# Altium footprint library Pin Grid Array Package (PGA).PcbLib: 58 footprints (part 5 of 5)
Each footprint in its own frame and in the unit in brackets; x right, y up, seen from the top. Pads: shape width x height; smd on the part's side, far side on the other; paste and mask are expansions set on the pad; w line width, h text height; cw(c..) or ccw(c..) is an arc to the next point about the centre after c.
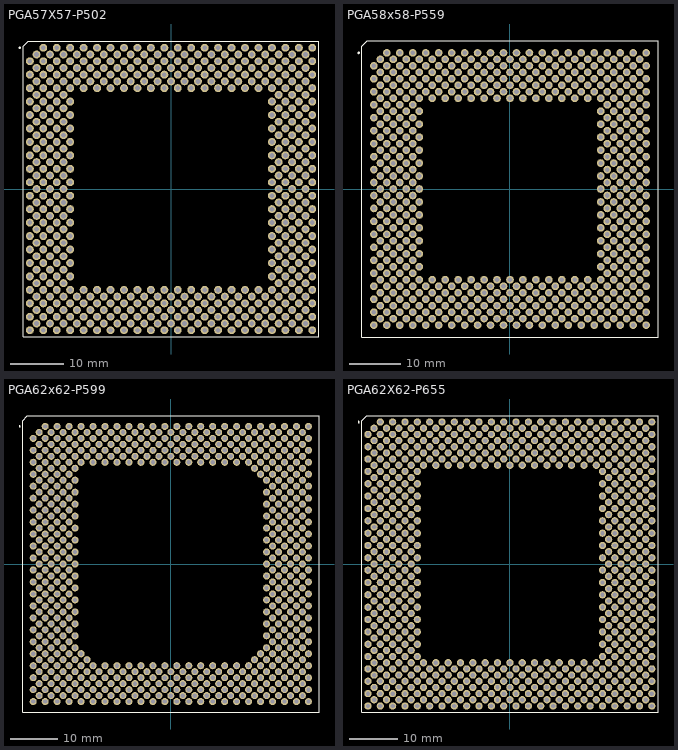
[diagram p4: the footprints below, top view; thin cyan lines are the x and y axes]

## PGA57X57-P502 [mm]
pads (503):
  round 1.5 hole 0.9: A3(-24.13,26.67) A5(-21.59,26.67) A7(-19.05,26.67) A9(-16.51,26.67) A11(-13.97,26.67) A13(-11.43,26.67) A15(-8.89,26.67) A17(-6.35,26.67) A19(-3.81,26.67) A21(-1.27,26.67) A23(1.27,26.67) A25(3.81,26.67) A27(6.35,26.67) A29(8.89,26.67) A31(11.43,26.67) A33(13.97,26.67) A35(16.51,26.67) A37(19.05,26.67) A39(21.59,26.67) A41(24.13,26.67) A43(26.67,26.67) AA1(-26.67,1.27) AA3(-24.13,1.27) AA5(-21.59,1.27) AA7(-19.05,1.27) AA37(19.05,1.27) AA39(21.59,1.27) AA41(24.13,1.27) AA43(26.67,1.27) AB2(-25.4,0) AB4(-22.86,0) AB6(-20.32,0) AB38(20.32,0) AB40(22.86,0) AB42(25.4,0) AC1(-26.67,-1.27) AC3(-24.13,-1.27) AC5(-21.59,-1.27) AC7(-19.05,-1.27) AC37(19.05,-1.27) AC39(21.59,-1.27) AC41(24.13,-1.27) AC43(26.67,-1.27) AD2(-25.4,-2.54) AD4(-22.86,-2.54) AD6(-20.32,-2.54) AD38(20.32,-2.54) AD40(22.86,-2.54) AD42(25.4,-2.54) AE1(-26.67,-3.81) AE3(-24.13,-3.81) AE5(-21.59,-3.81) AE7(-19.05,-3.81) AE37(19.05,-3.81) AE39(21.59,-3.81) AE41(24.13,-3.81) AE43(26.67,-3.81) AF2(-25.4,-5.08) AF4(-22.86,-5.08) AF6(-20.32,-5.08) AF38(20.32,-5.08) AF40(22.86,-5.08) AF42(25.4,-5.08) AG1(-26.67,-6.35) AG3(-24.13,-6.35) AG5(-21.59,-6.35) AG7(-19.05,-6.35) AG37(19.05,-6.35) AG39(21.59,-6.35) AG41(24.13,-6.35) AG43(26.67,-6.35) AH2(-25.4,-7.62) AH4(-22.86,-7.62) AH6(-20.32,-7.62) AH38(20.32,-7.62) AH40(22.86,-7.62) AH42(25.4,-7.62) AJ1(-26.67,-8.89) AJ3(-24.13,-8.89) AJ5(-21.59,-8.89) AJ7(-19.05,-8.89) AJ37(19.05,-8.89) AJ39(21.59,-8.89) AJ41(24.13,-8.89) AJ43(26.67,-8.89) AK2(-25.4,-10.16) AK4(-22.86,-10.16) AK6(-20.32,-10.16) AK38(20.32,-10.16) AK40(22.86,-10.16) AK42(25.4,-10.16) AL1(-26.67,-11.43) AL3(-24.13,-11.43) AL5(-21.59,-11.43) AL7(-19.05,-11.43) AL37(19.05,-11.43) AL39(21.59,-11.43) AL41(24.13,-11.43) AL43(26.67,-11.43) AM2(-25.4,-12.7) AM4(-22.86,-12.7) AM6(-20.32,-12.7) AM38(20.32,-12.7) AM40(22.86,-12.7) AM42(25.4,-12.7) AN1(-26.67,-13.97) AN3(-24.13,-13.97) AN5(-21.59,-13.97) AN7(-19.05,-13.97) AN37(19.05,-13.97) AN39(21.59,-13.97) AN41(24.13,-13.97) AN43(26.67,-13.97) AP2(-25.4,-15.24) AP4(-22.86,-15.24) AP6(-20.32,-15.24) AP38(20.32,-15.24) AP40(22.86,-15.24) AP42(25.4,-15.24) AR1(-26.67,-16.51) AR3(-24.13,-16.51) AR5(-21.59,-16.51) AR7(-19.05,-16.51) AR37(19.05,-16.51) AR39(21.59,-16.51) AR41(24.13,-16.51) AR43(26.67,-16.51) AT2(-25.4,-17.78) AT4(-22.86,-17.78) AT6(-20.32,-17.78) AT38(20.32,-17.78) AT40(22.86,-17.78) AT42(25.4,-17.78) AU1(-26.67,-19.05) AU3(-24.13,-19.05) AU5(-21.59,-19.05) AU7(-19.05,-19.05) AU9(-16.51,-19.05) AU11(-13.97,-19.05) AU13(-11.43,-19.05) AU15(-8.89,-19.05) AU17(-6.35,-19.05) AU19(-3.81,-19.05) AU21(-1.27,-19.05) AU23(1.27,-19.05) AU25(3.81,-19.05) AU27(6.35,-19.05) AU29(8.89,-19.05) AU31(11.43,-19.05) AU33(13.97,-19.05) AU35(16.51,-19.05) AU37(19.05,-19.05) AU39(21.59,-19.05) AU41(24.13,-19.05) AU43(26.67,-19.05) AV2(-25.4,-20.32) AV4(-22.86,-20.32) AV6(-20.32,-20.32) AV8(-17.78,-20.32) AV10(-15.24,-20.32) AV12(-12.7,-20.32) AV14(-10.16,-20.32) AV16(-7.62,-20.32) AV18(-5.08,-20.32) AV20(-2.54,-20.32) AV22(0,-20.32) AV24(2.54,-20.32) AV26(5.08,-20.32) AV28(7.62,-20.32) AV30(10.16,-20.32) AV32(12.7,-20.32) AV34(15.24,-20.32) AV36(17.78,-20.32) AV38(20.32,-20.32) AV40(22.86,-20.32) AV42(25.4,-20.32) AW1(-26.67,-21.59) AW3(-24.13,-21.59) AW5(-21.59,-21.59) AW7(-19.05,-21.59) AW9(-16.51,-21.59) AW11(-13.97,-21.59) AW13(-11.43,-21.59) AW15(-8.89,-21.59) AW17(-6.35,-21.59) AW19(-3.81,-21.59) AW21(-1.27,-21.59) AW23(1.27,-21.59) AW25(3.81,-21.59) AW27(6.35,-21.59) AW29(8.89,-21.59) AW31(11.43,-21.59) AW33(13.97,-21.59) AW35(16.51,-21.59) AW37(19.05,-21.59) AW39(21.59,-21.59) AW41(24.13,-21.59) AW43(26.67,-21.59) AY2(-25.4,-22.86) AY4(-22.86,-22.86) AY6(-20.32,-22.86) AY8(-17.78,-22.86) AY10(-15.24,-22.86) AY12(-12.7,-22.86) AY14(-10.16,-22.86) AY16(-7.62,-22.86) AY18(-5.08,-22.86) AY20(-2.54,-22.86) AY22(0,-22.86) AY24(2.54,-22.86) AY26(5.08,-22.86) AY28(7.62,-22.86) AY30(10.16,-22.86) AY32(12.7,-22.86) AY34(15.24,-22.86) AY36(17.78,-22.86) AY38(20.32,-22.86) AY40(22.86,-22.86) AY42(25.4,-22.86) B2(-25.4,25.4) B4(-22.86,25.4) B6(-20.32,25.4) B8(-17.78,25.4) B10(-15.24,25.4) B12(-12.7,25.4) B14(-10.16,25.4) B16(-7.62,25.4) B18(-5.08,25.4) B20(-2.54,25.4) B22(0,25.4) B24(2.54,25.4) B26(5.08,25.4) B28(7.62,25.4) B30(10.16,25.4) B32(12.7,25.4) B34(15.24,25.4) B36(17.78,25.4) B38(20.32,25.4) B40(22.86,25.4) B42(25.4,25.4) BA1(-26.67,-24.13) BA3(-24.13,-24.13) BA5(-21.59,-24.13) BA7(-19.05,-24.13) BA9(-16.51,-24.13) BA11(-13.97,-24.13) BA13(-11.43,-24.13) BA15(-8.89,-24.13) BA17(-6.35,-24.13) BA19(-3.81,-24.13) BA21(-1.27,-24.13) BA23(1.27,-24.13) BA25(3.81,-24.13) BA27(6.35,-24.13) BA29(8.89,-24.13) BA31(11.43,-24.13) BA33(13.97,-24.13) BA35(16.51,-24.13) BA37(19.05,-24.13) BA39(21.59,-24.13) BA41(24.13,-24.13) BA43(26.67,-24.13) BB2(-25.4,-25.4) BB4(-22.86,-25.4) BB6(-20.32,-25.4) BB8(-17.78,-25.4) BB10(-15.24,-25.4) BB12(-12.7,-25.4) BB14(-10.16,-25.4) BB16(-7.62,-25.4) BB18(-5.08,-25.4) BB20(-2.54,-25.4) BB22(0,-25.4) BB24(2.54,-25.4) BB26(5.08,-25.4) BB28(7.62,-25.4) BB30(10.16,-25.4) BB32(12.7,-25.4) BB34(15.24,-25.4) BB36(17.78,-25.4) BB38(20.32,-25.4) BB40(22.86,-25.4) BB42(25.4,-25.4) BC1(-26.67,-26.67) BC3(-24.13,-26.67) BC5(-21.59,-26.67) BC7(-19.05,-26.67) BC9(-16.51,-26.67) BC11(-13.97,-26.67) BC13(-11.43,-26.67) BC15(-8.89,-26.67) BC17(-6.35,-26.67) BC19(-3.81,-26.67) BC21(-1.27,-26.67) BC23(1.27,-26.67) BC25(3.81,-26.67) BC27(6.35,-26.67) BC29(8.89,-26.67) BC31(11.43,-26.67) BC33(13.97,-26.67) BC35(16.51,-26.67) BC37(19.05,-26.67) BC39(21.59,-26.67) BC41(24.13,-26.67) BC43(26.67,-26.67) C1(-26.67,24.13) C3(-24.13,24.13) C5(-21.59,24.13) C7(-19.05,24.13) C9(-16.51,24.13) C11(-13.97,24.13) C13(-11.43,24.13) C15(-8.89,24.13) C17(-6.35,24.13) C19(-3.81,24.13) C21(-1.27,24.13) C23(1.27,24.13) C25(3.81,24.13) C27(6.35,24.13) C29(8.89,24.13) C31(11.43,24.13) C33(13.97,24.13) C35(16.51,24.13) C37(19.05,24.13) C39(21.59,24.13) C41(24.13,24.13) C43(26.67,24.13) D2(-25.4,22.86) D4(-22.86,22.86) D6(-20.32,22.86) D8(-17.78,22.86) D10(-15.24,22.86) D12(-12.7,22.86) D14(-10.16,22.86) D16(-7.62,22.86) D18(-5.08,22.86) D20(-2.54,22.86) D22(0,22.86) D24(2.54,22.86) D26(5.08,22.86) D28(7.62,22.86) D30(10.16,22.86) D32(12.7,22.86) D34(15.24,22.86) D36(17.78,22.86) D38(20.32,22.86) D40(22.86,22.86) D42(25.4,22.86) E1(-26.67,21.59) E3(-24.13,21.59) E5(-21.59,21.59) E7(-19.05,21.59) E9(-16.51,21.59) E11(-13.97,21.59) E13(-11.43,21.59) E15(-8.89,21.59) E17(-6.35,21.59) E19(-3.81,21.59) E21(-1.27,21.59) E23(1.27,21.59) E25(3.81,21.59) E27(6.35,21.59) E29(8.89,21.59) E31(11.43,21.59) E33(13.97,21.59) E35(16.51,21.59) E37(19.05,21.59) E39(21.59,21.59) E41(24.13,21.59) E43(26.67,21.59) F2(-25.4,20.32) F4(-22.86,20.32) F6(-20.32,20.32) F8(-17.78,20.32) F10(-15.24,20.32) F12(-12.7,20.32) F14(-10.16,20.32) F16(-7.62,20.32) F18(-5.08,20.32) F20(-2.54,20.32) F22(0,20.32) F24(2.54,20.32) F26(5.08,20.32) F28(7.62,20.32) F30(10.16,20.32) F32(12.7,20.32) F34(15.24,20.32) F36(17.78,20.32) F38(20.32,20.32) F40(22.86,20.32) F42(25.4,20.32) G1(-26.67,19.05) G3(-24.13,19.05) G5(-21.59,19.05) G7(-19.05,19.05) G9(-16.51,19.05) G11(-13.97,19.05) G13(-11.43,19.05) G15(-8.89,19.05) G17(-6.35,19.05) G19(-3.81,19.05) G21(-1.27,19.05) G23(1.27,19.05) G25(3.81,19.05) G27(6.35,19.05) G29(8.89,19.05) G31(11.43,19.05) G33(13.97,19.05) G35(16.51,19.05) G37(19.05,19.05) G39(21.59,19.05) G41(24.13,19.05) G43(26.67,19.05) H2(-25.4,17.78) H4(-22.86,17.78) H6(-20.32,17.78) H38(20.32,17.78) H40(22.86,17.78) H42(25.4,17.78) J1(-26.67,16.51) J3(-24.13,16.51) J5(-21.59,16.51) J7(-19.05,16.51) J37(19.05,16.51) J39(21.59,16.51) J41(24.13,16.51) J43(26.67,16.51) K2(-25.4,15.24) K4(-22.86,15.24) K6(-20.32,15.24) K38(20.32,15.24) K40(22.86,15.24) K42(25.4,15.24) L1(-26.67,13.97) L3(-24.13,13.97) L5(-21.59,13.97) L7(-19.05,13.97) L37(19.05,13.97) L39(21.59,13.97) L41(24.13,13.97) L43(26.67,13.97) M2(-25.4,12.7) M4(-22.86,12.7) M6(-20.32,12.7) M38(20.32,12.7) M40(22.86,12.7) M42(25.4,12.7) N1(-26.67,11.43) N3(-24.13,11.43) N5(-21.59,11.43) N7(-19.05,11.43) N37(19.05,11.43) N39(21.59,11.43) N41(24.13,11.43) N43(26.67,11.43) P2(-25.4,10.16) P4(-22.86,10.16) P6(-20.32,10.16) P38(20.32,10.16) P40(22.86,10.16) P42(25.4,10.16) R1(-26.67,8.89) R3(-24.13,8.89) R5(-21.59,8.89) R7(-19.05,8.89) R37(19.05,8.89) R39(21.59,8.89) R41(24.13,8.89) R43(26.67,8.89) T2(-25.4,7.62) T4(-22.86,7.62) T6(-20.32,7.62) T38(20.32,7.62) T40(22.86,7.62) T42(25.4,7.62) U1(-26.67,6.35) U3(-24.13,6.35) U5(-21.59,6.35) U7(-19.05,6.35) U37(19.05,6.35) U39(21.59,6.35) U41(24.13,6.35) U43(26.67,6.35) V2(-25.4,5.08) V4(-22.86,5.08) V6(-20.32,5.08) V38(20.32,5.08) V40(22.86,5.08) V42(25.4,5.08) W1(-26.67,3.81) W3(-24.13,3.81) W5(-21.59,3.81) W7(-19.05,3.81) W37(19.05,3.81) W39(21.59,3.81) W41(24.13,3.81) W43(26.67,3.81) Y2(-25.4,2.54) Y4(-22.86,2.54) Y6(-20.32,2.54) Y38(20.32,2.54) Y40(22.86,2.54) Y42(25.4,2.54)
Top Overlay:
  circle w0.25: c-28.59,26.67 r0.125
  lines w0.2: -27.94,-27.94 -27.94,26.94 -26.94,27.94 27.94,27.94 27.94,-27.94 -27.94,-27.94

## PGA58x58-P559 [mm]
pads (559):
  round 1.5 hole 0.9: A3(-24.13,26.67) A5(-21.59,26.67) A7(-19.05,26.67) A9(-16.51,26.67) A11(-13.97,26.67) A13(-11.43,26.67) A15(-8.89,26.67) A17(-6.35,26.67) A19(-3.81,26.67) A21(-1.27,26.67) A23(1.27,26.67) A25(3.81,26.67) A27(6.35,26.67) A29(8.89,26.67) A31(11.43,26.67) A33(13.97,26.67) A35(16.51,26.67) A37(19.05,26.67) A39(21.59,26.67) A41(24.13,26.67) A43(26.67,26.67) AA1(-26.67,1.27) AA3(-24.13,1.27) AA5(-21.59,1.27) AA7(-19.05,1.27) AA37(19.05,1.27) AA39(21.59,1.27) AA41(24.13,1.27) AA43(26.67,1.27) AB2(-25.4,0) AB4(-22.86,0) AB6(-20.32,0) AB8(-17.78,0) AB36(17.78,0) AB38(20.32,0) AB40(22.86,0) AB42(25.4,0) AC1(-26.67,-1.27) AC3(-24.13,-1.27) AC5(-21.59,-1.27) AC7(-19.05,-1.27) AC37(19.05,-1.27) AC39(21.59,-1.27) AC41(24.13,-1.27) AC43(26.67,-1.27) AD2(-25.4,-2.54) AD4(-22.86,-2.54) AD6(-20.32,-2.54) AD8(-17.78,-2.54) AD36(17.78,-2.54) AD38(20.32,-2.54) AD40(22.86,-2.54) AD42(25.4,-2.54) AE1(-26.67,-3.81) AE3(-24.13,-3.81) AE5(-21.59,-3.81) AE7(-19.05,-3.81) AE37(19.05,-3.81) AE39(21.59,-3.81) AE41(24.13,-3.81) AE43(26.67,-3.81) AF2(-25.4,-5.08) AF4(-22.86,-5.08) AF6(-20.32,-5.08) AF8(-17.78,-5.08) AF36(17.78,-5.08) AF38(20.32,-5.08) AF40(22.86,-5.08) AF42(25.4,-5.08) AG1(-26.67,-6.35) AG3(-24.13,-6.35) AG5(-21.59,-6.35) AG7(-19.05,-6.35) AG37(19.05,-6.35) AG39(21.59,-6.35) AG41(24.13,-6.35) AG43(26.67,-6.35) AH2(-25.4,-7.62) AH4(-22.86,-7.62) AH6(-20.32,-7.62) AH8(-17.78,-7.62) AH36(17.78,-7.62) AH38(20.32,-7.62) AH40(22.86,-7.62) AH42(25.4,-7.62) AJ1(-26.67,-8.89) AJ3(-24.13,-8.89) AJ5(-21.59,-8.89) AJ7(-19.05,-8.89) AJ37(19.05,-8.89) AJ39(21.59,-8.89) AJ41(24.13,-8.89) AJ43(26.67,-8.89) AK2(-25.4,-10.16) AK4(-22.86,-10.16) AK6(-20.32,-10.16) AK8(-17.78,-10.16) AK36(17.78,-10.16) AK38(20.32,-10.16) AK40(22.86,-10.16) AK42(25.4,-10.16) AL1(-26.67,-11.43) AL3(-24.13,-11.43) AL5(-21.59,-11.43) AL7(-19.05,-11.43) AL37(19.05,-11.43) AL39(21.59,-11.43) AL41(24.13,-11.43) AL43(26.67,-11.43) AM2(-25.4,-12.7) AM4(-22.86,-12.7) AM6(-20.32,-12.7) AM8(-17.78,-12.7) AM36(17.78,-12.7) AM38(20.32,-12.7) AM40(22.86,-12.7) AM42(25.4,-12.7) AN1(-26.67,-13.97) AN3(-24.13,-13.97) AN5(-21.59,-13.97) AN7(-19.05,-13.97) AN37(19.05,-13.97) AN39(21.59,-13.97) AN41(24.13,-13.97) AN43(26.67,-13.97) AP2(-25.4,-15.24) AP4(-22.86,-15.24) AP6(-20.32,-15.24) AP8(-17.78,-15.24) AP36(17.78,-15.24) AP38(20.32,-15.24) AP40(22.86,-15.24) AP42(25.4,-15.24) AR1(-26.67,-16.51) AR3(-24.13,-16.51) AR5(-21.59,-16.51) AR7(-19.05,-16.51) AR37(19.05,-16.51) AR39(21.59,-16.51) AR41(24.13,-16.51) AR43(26.67,-16.51) AT2(-25.4,-17.78) AT4(-22.86,-17.78) AT6(-20.32,-17.78) AT8(-17.78,-17.78) AT10(-15.24,-17.78) AT12(-12.7,-17.78) AT14(-10.16,-17.78) AT16(-7.62,-17.78) AT18(-5.08,-17.78) AT20(-2.54,-17.78) AT22(0,-17.78) AT24(2.54,-17.78) AT26(5.08,-17.78) AT28(7.62,-17.78) AT30(10.16,-17.78) AT32(12.7,-17.78) AT34(15.24,-17.78) AT36(17.78,-17.78) AT38(20.32,-17.78) AT40(22.86,-17.78) AT42(25.4,-17.78) AU1(-26.67,-19.05) AU3(-24.13,-19.05) AU5(-21.59,-19.05) AU7(-19.05,-19.05) AU9(-16.51,-19.05) AU11(-13.97,-19.05) AU13(-11.43,-19.05) AU15(-8.89,-19.05) AU17(-6.35,-19.05) AU19(-3.81,-19.05) AU21(-1.27,-19.05) AU23(1.27,-19.05) AU25(3.81,-19.05) AU27(6.35,-19.05) AU29(8.89,-19.05) AU31(11.43,-19.05) AU33(13.97,-19.05) AU35(16.51,-19.05) AU37(19.05,-19.05) AU39(21.59,-19.05) AU41(24.13,-19.05) AU43(26.67,-19.05) AV2(-25.4,-20.32) AV4(-22.86,-20.32) AV6(-20.32,-20.32) AV8(-17.78,-20.32) AV10(-15.24,-20.32) AV12(-12.7,-20.32) AV14(-10.16,-20.32) AV16(-7.62,-20.32) AV18(-5.08,-20.32) AV20(-2.54,-20.32) AV22(0,-20.32) AV24(2.54,-20.32) AV26(5.08,-20.32) AV28(7.62,-20.32) AV30(10.16,-20.32) AV32(12.7,-20.32) AV34(15.24,-20.32) AV36(17.78,-20.32) AV38(20.32,-20.32) AV40(22.86,-20.32) AV42(25.4,-20.32) AW1(-26.67,-21.59) AW3(-24.13,-21.59) AW5(-21.59,-21.59) AW7(-19.05,-21.59) AW9(-16.51,-21.59) AW11(-13.97,-21.59) AW13(-11.43,-21.59) AW15(-8.89,-21.59) AW17(-6.35,-21.59) AW19(-3.81,-21.59) AW21(-1.27,-21.59) AW23(1.27,-21.59) AW25(3.81,-21.59) AW27(6.35,-21.59) AW29(8.89,-21.59) AW31(11.43,-21.59) AW33(13.97,-21.59) AW35(16.51,-21.59) AW37(19.05,-21.59) AW39(21.59,-21.59) AW41(24.13,-21.59) AW43(26.67,-21.59) AY2(-25.4,-22.86) AY4(-22.86,-22.86) AY6(-20.32,-22.86) AY8(-17.78,-22.86) AY10(-15.24,-22.86) AY12(-12.7,-22.86) AY14(-10.16,-22.86) AY16(-7.62,-22.86) AY18(-5.08,-22.86) AY20(-2.54,-22.86) AY22(0,-22.86) AY24(2.54,-22.86) AY26(5.08,-22.86) AY28(7.62,-22.86) AY30(10.16,-22.86) AY32(12.7,-22.86) AY34(15.24,-22.86) AY36(17.78,-22.86) AY38(20.32,-22.86) AY40(22.86,-22.86) AY42(25.4,-22.86) B2(-25.4,25.4) B4(-22.86,25.4) B6(-20.32,25.4) B8(-17.78,25.4) B10(-15.24,25.4) B12(-12.7,25.4) B14(-10.16,25.4) B16(-7.62,25.4) B18(-5.08,25.4) B20(-2.54,25.4) B22(0,25.4) B24(2.54,25.4) B26(5.08,25.4) B28(7.62,25.4) B30(10.16,25.4) B32(12.7,25.4) B34(15.24,25.4) B36(17.78,25.4) B38(20.32,25.4) B40(22.86,25.4) B42(25.4,25.4) BA1(-26.67,-24.13) BA3(-24.13,-24.13) BA5(-21.59,-24.13) BA7(-19.05,-24.13) BA9(-16.51,-24.13) BA11(-13.97,-24.13) BA13(-11.43,-24.13) BA15(-8.89,-24.13) BA17(-6.35,-24.13) BA19(-3.81,-24.13) BA21(-1.27,-24.13) BA23(1.27,-24.13) BA25(3.81,-24.13) BA27(6.35,-24.13) BA29(8.89,-24.13) BA31(11.43,-24.13) BA33(13.97,-24.13) BA35(16.51,-24.13) BA37(19.05,-24.13) BA39(21.59,-24.13) BA41(24.13,-24.13) BA43(26.67,-24.13) BB2(-25.4,-25.4) BB4(-22.86,-25.4) BB6(-20.32,-25.4) BB8(-17.78,-25.4) BB10(-15.24,-25.4) BB12(-12.7,-25.4) BB14(-10.16,-25.4) BB16(-7.62,-25.4) BB18(-5.08,-25.4) BB20(-2.54,-25.4) BB22(0,-25.4) BB24(2.54,-25.4) BB26(5.08,-25.4) BB28(7.62,-25.4) BB30(10.16,-25.4) BB32(12.7,-25.4) BB34(15.24,-25.4) BB36(17.78,-25.4) BB38(20.32,-25.4) BB40(22.86,-25.4) BB42(25.4,-25.4) BC1(-26.67,-26.67) BC3(-24.13,-26.67) BC5(-21.59,-26.67) BC7(-19.05,-26.67) BC9(-16.51,-26.67) BC11(-13.97,-26.67) BC13(-11.43,-26.67) BC15(-8.89,-26.67) BC17(-6.35,-26.67) BC19(-3.81,-26.67) BC21(-1.27,-26.67) BC23(1.27,-26.67) BC25(3.81,-26.67) BC27(6.35,-26.67) BC29(8.89,-26.67) BC31(11.43,-26.67) BC33(13.97,-26.67) BC35(16.51,-26.67) BC37(19.05,-26.67) BC39(21.59,-26.67) BC41(24.13,-26.67) BC43(26.67,-26.67) C1(-26.67,24.13) C3(-24.13,24.13) C5(-21.59,24.13) C7(-19.05,24.13) C9(-16.51,24.13) C11(-13.97,24.13) C13(-11.43,24.13) C15(-8.89,24.13) C17(-6.35,24.13) C19(-3.81,24.13) C21(-1.27,24.13) C23(1.27,24.13) C25(3.81,24.13) C27(6.35,24.13) C29(8.89,24.13) C31(11.43,24.13) C33(13.97,24.13) C35(16.51,24.13) C37(19.05,24.13) C39(21.59,24.13) C41(24.13,24.13) C43(26.67,24.13) D2(-25.4,22.86) D4(-22.86,22.86) D6(-20.32,22.86) D8(-17.78,22.86) D10(-15.24,22.86) D12(-12.7,22.86) D14(-10.16,22.86) D16(-7.62,22.86) D18(-5.08,22.86) D20(-2.54,22.86) D22(0,22.86) D24(2.54,22.86) D26(5.08,22.86) D28(7.62,22.86) D30(10.16,22.86) D32(12.7,22.86) D34(15.24,22.86) D36(17.78,22.86) D38(20.32,22.86) D40(22.86,22.86) D42(25.4,22.86) E1(-26.67,21.59) E3(-24.13,21.59) E5(-21.59,21.59) E7(-19.05,21.59) E9(-16.51,21.59) E11(-13.97,21.59) E13(-11.43,21.59) E15(-8.89,21.59) E17(-6.35,21.59) E19(-3.81,21.59) E21(-1.27,21.59) E23(1.27,21.59) E25(3.81,21.59) E27(6.35,21.59) E29(8.89,21.59) E31(11.43,21.59) E33(13.97,21.59) E35(16.51,21.59) E37(19.05,21.59) E39(21.59,21.59) E41(24.13,21.59) E43(26.67,21.59) F2(-25.4,20.32) F4(-22.86,20.32) F6(-20.32,20.32) F8(-17.78,20.32) F10(-15.24,20.32) F12(-12.7,20.32) F14(-10.16,20.32) F16(-7.62,20.32) F18(-5.08,20.32) F20(-2.54,20.32) F22(0,20.32) F24(2.54,20.32) F26(5.08,20.32) F28(7.62,20.32) F30(10.16,20.32) F32(12.7,20.32) F34(15.24,20.32) F36(17.78,20.32) F38(20.32,20.32) F40(22.86,20.32) F42(25.4,20.32) G1(-26.67,19.05) G3(-24.13,19.05) G5(-21.59,19.05) G7(-19.05,19.05) G9(-16.51,19.05) G11(-13.97,19.05) G13(-11.43,19.05) G15(-8.89,19.05) G17(-6.35,19.05) G19(-3.81,19.05) G21(-1.27,19.05) G23(1.27,19.05) G25(3.81,19.05) G27(6.35,19.05) G29(8.89,19.05) G31(11.43,19.05) G33(13.97,19.05) G35(16.51,19.05) G37(19.05,19.05) G39(21.59,19.05) G41(24.13,19.05) G43(26.67,19.05) H2(-25.4,17.78) H4(-22.86,17.78) H6(-20.32,17.78) H8(-17.78,17.78) H10(-15.24,17.78) H12(-12.7,17.78) H14(-10.16,17.78) H16(-7.62,17.78) H18(-5.08,17.78) H20(-2.54,17.78) H22(0,17.78) H24(2.54,17.78) H26(5.08,17.78) H28(7.62,17.78) H30(10.16,17.78) H32(12.7,17.78) H34(15.24,17.78) H36(17.78,17.78) H38(20.32,17.78) H40(22.86,17.78) H42(25.4,17.78) J1(-26.67,16.51) J3(-24.13,16.51) J5(-21.59,16.51) J7(-19.05,16.51) J37(19.05,16.51) J39(21.59,16.51) J41(24.13,16.51) J43(26.67,16.51) K2(-25.4,15.24) K4(-22.86,15.24) K6(-20.32,15.24) K8(-17.78,15.24) K36(17.78,15.24) K38(20.32,15.24) K40(22.86,15.24) K42(25.4,15.24) L1(-26.67,13.97) L3(-24.13,13.97) L5(-21.59,13.97) L7(-19.05,13.97) L37(19.05,13.97) L39(21.59,13.97) L41(24.13,13.97) L43(26.67,13.97) M2(-25.4,12.7) M4(-22.86,12.7) M6(-20.32,12.7) M8(-17.78,12.7) M36(17.78,12.7) M38(20.32,12.7) M40(22.86,12.7) M42(25.4,12.7) N1(-26.67,11.43) N3(-24.13,11.43) N5(-21.59,11.43) N7(-19.05,11.43) N37(19.05,11.43) N39(21.59,11.43) N41(24.13,11.43) N43(26.67,11.43) P2(-25.4,10.16) P4(-22.86,10.16) P6(-20.32,10.16) P8(-17.78,10.16) P36(17.78,10.16) P38(20.32,10.16) P40(22.86,10.16) P42(25.4,10.16) R1(-26.67,8.89) R3(-24.13,8.89) R5(-21.59,8.89) R7(-19.05,8.89) R37(19.05,8.89) R39(21.59,8.89) R41(24.13,8.89) R43(26.67,8.89) T2(-25.4,7.62) T4(-22.86,7.62) T6(-20.32,7.62) T8(-17.78,7.62) T36(17.78,7.62) T38(20.32,7.62) T40(22.86,7.62) T42(25.4,7.62) U1(-26.67,6.35) U3(-24.13,6.35) U5(-21.59,6.35) U7(-19.05,6.35) U37(19.05,6.35) U39(21.59,6.35) U41(24.13,6.35) U43(26.67,6.35) V2(-25.4,5.08) V4(-22.86,5.08) V6(-20.32,5.08) V8(-17.78,5.08) V36(17.78,5.08) V38(20.32,5.08) V40(22.86,5.08) V42(25.4,5.08) W1(-26.67,3.81) W3(-24.13,3.81) W5(-21.59,3.81) W7(-19.05,3.81) W37(19.05,3.81) W39(21.59,3.81) W41(24.13,3.81) W43(26.67,3.81) Y2(-25.4,2.54) Y4(-22.86,2.54) Y6(-20.32,2.54) Y8(-17.78,2.54) Y36(17.78,2.54) Y38(20.32,2.54) Y40(22.86,2.54) Y42(25.4,2.54)
Top Overlay:
  circle w0.25: c-29.65,26.67 r0.125
  lines w0.2: -29,-29 29,-29 29,29 -28,29 -29,28 -29,-29

## PGA62x62-P599 [mm]
pads (599):
  round 1.5 hole 0.9: A3(-26.67,29.21) A5(-24.13,29.21) A7(-21.59,29.21) A9(-19.05,29.21) A11(-16.51,29.21) A13(-13.97,29.21) A15(-11.43,29.21) A17(-8.89,29.21) A19(-6.35,29.21) A21(-3.81,29.21) A23(-1.27,29.21) A25(1.27,29.21) A27(3.81,29.21) A29(6.35,29.21) A31(8.89,29.21) A33(11.43,29.21) A35(13.97,29.21) A37(16.51,29.21) A39(19.05,29.21) A41(21.59,29.21) A43(24.13,29.21) A45(26.67,29.21) A47(29.21,29.21) AA1(-29.21,3.81) AA3(-26.67,3.81) AA5(-24.13,3.81) AA7(-21.59,3.81) AA41(21.59,3.81) AA43(24.13,3.81) AA45(26.67,3.81) AA47(29.21,3.81) AB2(-27.94,2.54) AB4(-25.4,2.54) AB6(-22.86,2.54) AB8(-20.32,2.54) AB40(20.32,2.54) AB42(22.86,2.54) AB44(25.4,2.54) AB46(27.94,2.54) AC1(-29.21,1.27) AC3(-26.67,1.27) AC5(-24.13,1.27) AC7(-21.59,1.27) AC41(21.59,1.27) AC43(24.13,1.27) AC45(26.67,1.27) AC47(29.21,1.27) AD2(-27.94,0) AD4(-25.4,0) AD6(-22.86,0) AD8(-20.32,0) AD40(20.32,0) AD42(22.86,0) AD44(25.4,0) AD46(27.94,0) AE1(-29.21,-1.27) AE3(-26.67,-1.27) AE5(-24.13,-1.27) AE7(-21.59,-1.27) AE41(21.59,-1.27) AE43(24.13,-1.27) AE45(26.67,-1.27) AE47(29.21,-1.27) AF2(-27.94,-2.54) AF4(-25.4,-2.54) AF6(-22.86,-2.54) AF8(-20.32,-2.54) AF40(20.32,-2.54) AF42(22.86,-2.54) AF44(25.4,-2.54) AF46(27.94,-2.54) AG1(-29.21,-3.81) AG3(-26.67,-3.81) AG5(-24.13,-3.81) AG7(-21.59,-3.81) AG41(21.59,-3.81) AG43(24.13,-3.81) AG45(26.67,-3.81) AG47(29.21,-3.81) AH2(-27.94,-5.08) AH4(-25.4,-5.08) AH6(-22.86,-5.08) AH8(-20.32,-5.08) AH40(20.32,-5.08) AH42(22.86,-5.08) AH44(25.4,-5.08) AH46(27.94,-5.08) AJ1(-29.21,-6.35) AJ3(-26.67,-6.35) AJ5(-24.13,-6.35) AJ7(-21.59,-6.35) AJ41(21.59,-6.35) AJ43(24.13,-6.35) AJ45(26.67,-6.35) AJ47(29.21,-6.35) AK2(-27.94,-7.62) AK4(-25.4,-7.62) AK6(-22.86,-7.62) AK8(-20.32,-7.62) AK40(20.32,-7.62) AK42(22.86,-7.62) AK44(25.4,-7.62) AK46(27.94,-7.62) AL1(-29.21,-8.89) AL3(-26.67,-8.89) AL5(-24.13,-8.89) AL7(-21.59,-8.89) AL41(21.59,-8.89) AL43(24.13,-8.89) AL45(26.67,-8.89) AL47(29.21,-8.89) AM2(-27.94,-10.16) AM4(-25.4,-10.16) AM6(-22.86,-10.16) AM8(-20.32,-10.16) AM40(20.32,-10.16) AM42(22.86,-10.16) AM44(25.4,-10.16) AM46(27.94,-10.16) AN1(-29.21,-11.43) AN3(-26.67,-11.43) AN5(-24.13,-11.43) AN7(-21.59,-11.43) AN41(21.59,-11.43) AN43(24.13,-11.43) AN45(26.67,-11.43) AN47(29.21,-11.43) AP2(-27.94,-12.7) AP4(-25.4,-12.7) AP6(-22.86,-12.7) AP8(-20.32,-12.7) AP40(20.32,-12.7) AP42(22.86,-12.7) AP44(25.4,-12.7) AP46(27.94,-12.7) AR1(-29.21,-13.97) AR3(-26.67,-13.97) AR5(-24.13,-13.97) AR7(-21.59,-13.97) AR41(21.59,-13.97) AR43(24.13,-13.97) AR45(26.67,-13.97) AR47(29.21,-13.97) AT2(-27.94,-15.24) AT4(-25.4,-15.24) AT6(-22.86,-15.24) AT8(-20.32,-15.24) AT40(20.32,-15.24) AT42(22.86,-15.24) AT44(25.4,-15.24) AT46(27.94,-15.24) AU1(-29.21,-16.51) AU3(-26.67,-16.51) AU5(-24.13,-16.51) AU7(-21.59,-16.51) AU41(21.59,-16.51) AU43(24.13,-16.51) AU45(26.67,-16.51) AU47(29.21,-16.51) AV2(-27.94,-17.78) AV4(-25.4,-17.78) AV6(-22.86,-17.78) AV8(-20.32,-17.78) AV40(20.32,-17.78) AV42(22.86,-17.78) AV44(25.4,-17.78) AV46(27.94,-17.78) AW1(-29.21,-19.05) AW3(-26.67,-19.05) AW5(-24.13,-19.05) AW7(-21.59,-19.05) AW9(-19.05,-19.05) AW39(19.05,-19.05) AW41(21.59,-19.05) AW43(24.13,-19.05) AW45(26.67,-19.05) AW47(29.21,-19.05) AY2(-27.94,-20.32) AY4(-25.4,-20.32) AY6(-22.86,-20.32) AY8(-20.32,-20.32) AY10(-17.78,-20.32) AY38(17.78,-20.32) AY40(20.32,-20.32) AY42(22.86,-20.32) AY44(25.4,-20.32) AY46(27.94,-20.32) B2(-27.94,27.94) B4(-25.4,27.94) B6(-22.86,27.94) B8(-20.32,27.94) B10(-17.78,27.94) B12(-15.24,27.94) B14(-12.7,27.94) B16(-10.16,27.94) B18(-7.62,27.94) B20(-5.08,27.94) B22(-2.54,27.94) B24(0,27.94) B26(2.54,27.94) B28(5.08,27.94) B30(7.62,27.94) B32(10.16,27.94) B34(12.7,27.94) B36(15.24,27.94) B38(17.78,27.94) B40(20.32,27.94) B42(22.86,27.94) B44(25.4,27.94) B46(27.94,27.94) BA1(-29.21,-21.59) BA3(-26.67,-21.59) BA5(-24.13,-21.59) BA7(-21.59,-21.59) BA9(-19.05,-21.59) BA11(-16.51,-21.59) BA13(-13.97,-21.59) BA15(-11.43,-21.59) BA17(-8.89,-21.59) BA19(-6.35,-21.59) BA21(-3.81,-21.59) BA23(-1.27,-21.59) BA25(1.27,-21.59) BA27(3.81,-21.59) BA29(6.35,-21.59) BA31(8.89,-21.59) BA33(11.43,-21.59) BA35(13.97,-21.59) BA37(16.51,-21.59) BA39(19.05,-21.59) BA41(21.59,-21.59) BA43(24.13,-21.59) BA45(26.67,-21.59) BA47(29.21,-21.59) BB2(-27.94,-22.86) BB4(-25.4,-22.86) BB6(-22.86,-22.86) BB8(-20.32,-22.86) BB10(-17.78,-22.86) BB12(-15.24,-22.86) BB14(-12.7,-22.86) BB16(-10.16,-22.86) BB18(-7.62,-22.86) BB20(-5.08,-22.86) BB22(-2.54,-22.86) BB24(0,-22.86) BB26(2.54,-22.86) BB28(5.08,-22.86) BB30(7.62,-22.86) BB32(10.16,-22.86) BB34(12.7,-22.86) BB36(15.24,-22.86) BB38(17.78,-22.86) BB40(20.32,-22.86) BB42(22.86,-22.86) BB44(25.4,-22.86) BB46(27.94,-22.86) BC1(-29.21,-24.13) BC3(-26.67,-24.13) BC5(-24.13,-24.13) BC7(-21.59,-24.13) BC9(-19.05,-24.13) BC11(-16.51,-24.13) BC13(-13.97,-24.13) BC15(-11.43,-24.13) BC17(-8.89,-24.13) BC19(-6.35,-24.13) BC21(-3.81,-24.13) BC23(-1.27,-24.13) BC25(1.27,-24.13) BC27(3.81,-24.13) BC29(6.35,-24.13) BC31(8.89,-24.13) BC33(11.43,-24.13) BC35(13.97,-24.13) BC37(16.51,-24.13) BC39(19.05,-24.13) BC41(21.59,-24.13) BC43(24.13,-24.13) BC45(26.67,-24.13) BC47(29.21,-24.13) BD2(-27.94,-25.4) BD4(-25.4,-25.4) BD6(-22.86,-25.4) BD8(-20.32,-25.4) BD10(-17.78,-25.4) BD12(-15.24,-25.4) BD14(-12.7,-25.4) BD16(-10.16,-25.4) BD18(-7.62,-25.4) BD20(-5.08,-25.4) BD22(-2.54,-25.4) BD24(0,-25.4) BD26(2.54,-25.4) BD28(5.08,-25.4) BD30(7.62,-25.4) BD32(10.16,-25.4) BD34(12.7,-25.4) BD36(15.24,-25.4) BD38(17.78,-25.4) BD40(20.32,-25.4) BD42(22.86,-25.4) BD44(25.4,-25.4) BD46(27.94,-25.4) BE1(-29.21,-26.67) BE3(-26.67,-26.67) BE5(-24.13,-26.67) BE7(-21.59,-26.67) BE9(-19.05,-26.67) BE11(-16.51,-26.67) BE13(-13.97,-26.67) BE15(-11.43,-26.67) BE17(-8.89,-26.67) BE19(-6.35,-26.67) BE21(-3.81,-26.67) BE23(-1.27,-26.67) BE25(1.27,-26.67) BE27(3.81,-26.67) BE29(6.35,-26.67) BE31(8.89,-26.67) BE33(11.43,-26.67) BE35(13.97,-26.67) BE37(16.51,-26.67) BE39(19.05,-26.67) BE41(21.59,-26.67) BE43(24.13,-26.67) BE45(26.67,-26.67) BE47(29.21,-26.67) BF2(-27.94,-27.94) BF4(-25.4,-27.94) BF6(-22.86,-27.94) BF8(-20.32,-27.94) BF10(-17.78,-27.94) BF12(-15.24,-27.94) BF14(-12.7,-27.94) BF16(-10.16,-27.94) BF18(-7.62,-27.94) BF20(-5.08,-27.94) BF22(-2.54,-27.94) BF24(0,-27.94) BF26(2.54,-27.94) BF28(5.08,-27.94) BF30(7.62,-27.94) BF32(10.16,-27.94) BF34(12.7,-27.94) BF36(15.24,-27.94) BF38(17.78,-27.94) BF40(20.32,-27.94) BF42(22.86,-27.94) BF44(25.4,-27.94) BF46(27.94,-27.94) BG1(-29.21,-29.21) BG3(-26.67,-29.21) BG5(-24.13,-29.21) BG7(-21.59,-29.21) BG9(-19.05,-29.21) BG11(-16.51,-29.21) BG13(-13.97,-29.21) BG15(-11.43,-29.21) BG17(-8.89,-29.21) BG19(-6.35,-29.21) BG21(-3.81,-29.21) BG23(-1.27,-29.21) BG25(1.27,-29.21) BG27(3.81,-29.21) BG29(6.35,-29.21) BG31(8.89,-29.21) BG33(11.43,-29.21) BG35(13.97,-29.21) BG37(16.51,-29.21) BG39(19.05,-29.21) BG41(21.59,-29.21) BG43(24.13,-29.21) BG45(26.67,-29.21) BG47(29.21,-29.21) C1(-29.21,26.67) C3(-26.67,26.67) C5(-24.13,26.67) C7(-21.59,26.67) C9(-19.05,26.67) C11(-16.51,26.67) C13(-13.97,26.67) C15(-11.43,26.67) C17(-8.89,26.67) C19(-6.35,26.67) C21(-3.81,26.67) C23(-1.27,26.67) C25(1.27,26.67) C27(3.81,26.67) C29(6.35,26.67) C31(8.89,26.67) C33(11.43,26.67) C35(13.97,26.67) C37(16.51,26.67) C39(19.05,26.67) C41(21.59,26.67) C43(24.13,26.67) C45(26.67,26.67) C47(29.21,26.67) D2(-27.94,25.4) D4(-25.4,25.4) D6(-22.86,25.4) D8(-20.32,25.4) D10(-17.78,25.4) D12(-15.24,25.4) D14(-12.7,25.4) D16(-10.16,25.4) D18(-7.62,25.4) D20(-5.08,25.4) D22(-2.54,25.4) D24(0,25.4) D26(2.54,25.4) D28(5.08,25.4) D30(7.62,25.4) D32(10.16,25.4) D34(12.7,25.4) D36(15.24,25.4) D38(17.78,25.4) D40(20.32,25.4) D42(22.86,25.4) D44(25.4,25.4) D46(27.94,25.4) E1(-29.21,24.13) E3(-26.67,24.13) E5(-24.13,24.13) E7(-21.59,24.13) E9(-19.05,24.13) E11(-16.51,24.13) E13(-13.97,24.13) E15(-11.43,24.13) E17(-8.89,24.13) E19(-6.35,24.13) E21(-3.81,24.13) E23(-1.27,24.13) E25(1.27,24.13) E27(3.81,24.13) E29(6.35,24.13) E31(8.89,24.13) E33(11.43,24.13) E35(13.97,24.13) E37(16.51,24.13) E39(19.05,24.13) E41(21.59,24.13) E43(24.13,24.13) E45(26.67,24.13) E47(29.21,24.13) F2(-27.94,22.86) F4(-25.4,22.86) F6(-22.86,22.86) F8(-20.32,22.86) F10(-17.78,22.86) F12(-15.24,22.86) F14(-12.7,22.86) F16(-10.16,22.86) F18(-7.62,22.86) F20(-5.08,22.86) F22(-2.54,22.86) F24(0,22.86) F26(2.54,22.86) F28(5.08,22.86) F30(7.62,22.86) F32(10.16,22.86) F34(12.7,22.86) F36(15.24,22.86) F38(17.78,22.86) F40(20.32,22.86) F42(22.86,22.86) F44(25.4,22.86) F46(27.94,22.86) G1(-29.21,21.59) G3(-26.67,21.59) G5(-24.13,21.59) G7(-21.59,21.59) G9(-19.05,21.59) G11(-16.51,21.59) G13(-13.97,21.59) G15(-11.43,21.59) G17(-8.89,21.59) G19(-6.35,21.59) G21(-3.81,21.59) G23(-1.27,21.59) G25(1.27,21.59) G27(3.81,21.59) G29(6.35,21.59) G31(8.89,21.59) G33(11.43,21.59) G35(13.97,21.59) G37(16.51,21.59) G39(19.05,21.59) G41(21.59,21.59) G43(24.13,21.59) G45(26.67,21.59) G47(29.21,21.59) H2(-27.94,20.32) H4(-25.4,20.32) H6(-22.86,20.32) H8(-20.32,20.32) H38(17.78,20.32) H40(20.32,20.32) H42(22.86,20.32) H44(25.4,20.32) H46(27.94,20.32) J1(-29.21,19.05) J3(-26.67,19.05) J5(-24.13,19.05) J7(-21.59,19.05) J39(19.05,19.05) J41(21.59,19.05) J43(24.13,19.05) J45(26.67,19.05) J47(29.21,19.05) K2(-27.94,17.78) K4(-25.4,17.78) K6(-22.86,17.78) K8(-20.32,17.78) K40(20.32,17.78) K42(22.86,17.78) K44(25.4,17.78) K46(27.94,17.78) L1(-29.21,16.51) L3(-26.67,16.51) L5(-24.13,16.51) L7(-21.59,16.51) L41(21.59,16.51) L43(24.13,16.51) L45(26.67,16.51) L47(29.21,16.51) M2(-27.94,15.24) M4(-25.4,15.24) M6(-22.86,15.24) M8(-20.32,15.24) M40(20.32,15.24) M42(22.86,15.24) M44(25.4,15.24) M46(27.94,15.24) N1(-29.21,13.97) N3(-26.67,13.97) N5(-24.13,13.97) N7(-21.59,13.97) N41(21.59,13.97) N43(24.13,13.97) N45(26.67,13.97) N47(29.21,13.97) P2(-27.94,12.7) P4(-25.4,12.7) P6(-22.86,12.7) P8(-20.32,12.7) P40(20.32,12.7) P42(22.86,12.7) P44(25.4,12.7) P46(27.94,12.7) R1(-29.21,11.43) R3(-26.67,11.43) R5(-24.13,11.43) R7(-21.59,11.43) R41(21.59,11.43) R43(24.13,11.43) R45(26.67,11.43) R47(29.21,11.43) T2(-27.94,10.16) T4(-25.4,10.16) T6(-22.86,10.16) T8(-20.32,10.16) T40(20.32,10.16) T42(22.86,10.16) T44(25.4,10.16) T46(27.94,10.16) U1(-29.21,8.89) U3(-26.67,8.89) U5(-24.13,8.89) U7(-21.59,8.89) U41(21.59,8.89) U43(24.13,8.89) U45(26.67,8.89) U47(29.21,8.89) V2(-27.94,7.62) V4(-25.4,7.62) V6(-22.86,7.62) V8(-20.32,7.62) V40(20.32,7.62) V42(22.86,7.62) V44(25.4,7.62) V46(27.94,7.62) W1(-29.21,6.35) W3(-26.67,6.35) W5(-24.13,6.35) W7(-21.59,6.35) W41(21.59,6.35) W43(24.13,6.35) W45(26.67,6.35) W47(29.21,6.35) Y2(-27.94,5.08) Y4(-25.4,5.08) Y6(-22.86,5.08) Y8(-20.32,5.08) Y40(20.32,5.08) Y42(22.86,5.08) Y44(25.4,5.08) Y46(27.94,5.08)
Top Overlay:
  circle w0.25: c-32.1,29.21 r0.125
  lines w0.2: -31.45,-31.45 -31.45,30.45 -30.45,31.45 31.45,31.45 31.45,-31.45 -31.45,-31.45

## PGA62X62-P655 [mm]
pads (655):
  round 1.5 hole 0.9: A3(-26.67,29.21) A5(-24.13,29.21) A7(-21.59,29.21) A9(-19.05,29.21) A11(-16.51,29.21) A13(-13.97,29.21) A15(-11.43,29.21) A17(-8.89,29.21) A19(-6.35,29.21) A21(-3.81,29.21) A23(-1.27,29.21) A25(1.27,29.21) A27(3.81,29.21) A29(6.35,29.21) A31(8.89,29.21) A33(11.43,29.21) A35(13.97,29.21) A37(16.51,29.21) A39(19.05,29.21) A41(21.59,29.21) A43(24.13,29.21) A45(26.67,29.21) A47(29.21,29.21) AA1(-29.21,3.81) AA3(-26.67,3.81) AA5(-24.13,3.81) AA7(-21.59,3.81) AA9(-19.05,3.81) AA39(19.05,3.81) AA41(21.59,3.81) AA43(24.13,3.81) AA45(26.67,3.81) AA47(29.21,3.81) AB2(-27.94,2.54) AB4(-25.4,2.54) AB6(-22.86,2.54) AB8(-20.32,2.54) AB40(20.32,2.54) AB42(22.86,2.54) AB44(25.4,2.54) AB46(27.94,2.54) AC1(-29.21,1.27) AC3(-26.67,1.27) AC5(-24.13,1.27) AC7(-21.59,1.27) AC9(-19.05,1.27) AC39(19.05,1.27) AC41(21.59,1.27) AC43(24.13,1.27) AC45(26.67,1.27) AC47(29.21,1.27) AD2(-27.94,0) AD4(-25.4,0) AD6(-22.86,0) AD8(-20.32,0) AD40(20.32,0) AD42(22.86,0) AD44(25.4,0) AD46(27.94,0) AE1(-29.21,-1.27) AE3(-26.67,-1.27) AE5(-24.13,-1.27) AE7(-21.59,-1.27) AE9(-19.05,-1.27) AE39(19.05,-1.27) AE41(21.59,-1.27) AE43(24.13,-1.27) AE45(26.67,-1.27) AE47(29.21,-1.27) AF2(-27.94,-2.54) AF4(-25.4,-2.54) AF6(-22.86,-2.54) AF8(-20.32,-2.54) AF40(20.32,-2.54) AF42(22.86,-2.54) AF44(25.4,-2.54) AF46(27.94,-2.54) AG1(-29.21,-3.81) AG3(-26.67,-3.81) AG5(-24.13,-3.81) AG7(-21.59,-3.81) AG9(-19.05,-3.81) AG39(19.05,-3.81) AG41(21.59,-3.81) AG43(24.13,-3.81) AG45(26.67,-3.81) AG47(29.21,-3.81) AH2(-27.94,-5.08) AH4(-25.4,-5.08) AH6(-22.86,-5.08) AH8(-20.32,-5.08) AH40(20.32,-5.08) AH42(22.86,-5.08) AH44(25.4,-5.08) AH46(27.94,-5.08) AJ1(-29.21,-6.35) AJ3(-26.67,-6.35) AJ5(-24.13,-6.35) AJ7(-21.59,-6.35) AJ9(-19.05,-6.35) AJ39(19.05,-6.35) AJ41(21.59,-6.35) AJ43(24.13,-6.35) AJ45(26.67,-6.35) AJ47(29.21,-6.35) AK2(-27.94,-7.62) AK4(-25.4,-7.62) AK6(-22.86,-7.62) AK8(-20.32,-7.62) AK40(20.32,-7.62) AK42(22.86,-7.62) AK44(25.4,-7.62) AK46(27.94,-7.62) AL1(-29.21,-8.89) AL3(-26.67,-8.89) AL5(-24.13,-8.89) AL7(-21.59,-8.89) AL9(-19.05,-8.89) AL39(19.05,-8.89) AL41(21.59,-8.89) AL43(24.13,-8.89) AL45(26.67,-8.89) AL47(29.21,-8.89) AM2(-27.94,-10.16) AM4(-25.4,-10.16) AM6(-22.86,-10.16) AM8(-20.32,-10.16) AM40(20.32,-10.16) AM42(22.86,-10.16) AM44(25.4,-10.16) AM46(27.94,-10.16) AN1(-29.21,-11.43) AN3(-26.67,-11.43) AN5(-24.13,-11.43) AN7(-21.59,-11.43) AN9(-19.05,-11.43) AN39(19.05,-11.43) AN41(21.59,-11.43) AN43(24.13,-11.43) AN45(26.67,-11.43) AN47(29.21,-11.43) AP2(-27.94,-12.7) AP4(-25.4,-12.7) AP6(-22.86,-12.7) AP8(-20.32,-12.7) AP40(20.32,-12.7) AP42(22.86,-12.7) AP44(25.4,-12.7) AP46(27.94,-12.7) AR1(-29.21,-13.97) AR3(-26.67,-13.97) AR5(-24.13,-13.97) AR7(-21.59,-13.97) AR9(-19.05,-13.97) AR39(19.05,-13.97) AR41(21.59,-13.97) AR43(24.13,-13.97) AR45(26.67,-13.97) AR47(29.21,-13.97) AT2(-27.94,-15.24) AT4(-25.4,-15.24) AT6(-22.86,-15.24) AT8(-20.32,-15.24) AT40(20.32,-15.24) AT42(22.86,-15.24) AT44(25.4,-15.24) AT46(27.94,-15.24) AU1(-29.21,-16.51) AU3(-26.67,-16.51) AU5(-24.13,-16.51) AU7(-21.59,-16.51) AU9(-19.05,-16.51) AU39(19.05,-16.51) AU41(21.59,-16.51) AU43(24.13,-16.51) AU45(26.67,-16.51) AU47(29.21,-16.51) AV2(-27.94,-17.78) AV4(-25.4,-17.78) AV6(-22.86,-17.78) AV8(-20.32,-17.78) AV40(20.32,-17.78) AV42(22.86,-17.78) AV44(25.4,-17.78) AV46(27.94,-17.78) AW1(-29.21,-19.05) AW3(-26.67,-19.05) AW5(-24.13,-19.05) AW7(-21.59,-19.05) AW9(-19.05,-19.05) AW39(19.05,-19.05) AW41(21.59,-19.05) AW43(24.13,-19.05) AW45(26.67,-19.05) AW47(29.21,-19.05) AY2(-27.94,-20.32) AY4(-25.4,-20.32) AY6(-22.86,-20.32) AY8(-20.32,-20.32) AY10(-17.78,-20.32) AY12(-15.24,-20.32) AY14(-12.7,-20.32) AY16(-10.16,-20.32) AY18(-7.62,-20.32) AY20(-5.08,-20.32) AY22(-2.54,-20.32) AY24(0,-20.32) AY26(2.54,-20.32) AY28(5.08,-20.32) AY30(7.62,-20.32) AY32(10.16,-20.32) AY34(12.7,-20.32) AY36(15.24,-20.32) AY38(17.78,-20.32) AY40(20.32,-20.32) AY42(22.86,-20.32) AY44(25.4,-20.32) AY46(27.94,-20.32) B2(-27.94,27.94) B4(-25.4,27.94) B6(-22.86,27.94) B8(-20.32,27.94) B10(-17.78,27.94) B12(-15.24,27.94) B14(-12.7,27.94) B16(-10.16,27.94) B18(-7.62,27.94) B20(-5.08,27.94) B22(-2.54,27.94) B24(0,27.94) B26(2.54,27.94) B28(5.08,27.94) B30(7.62,27.94) B32(10.16,27.94) B34(12.7,27.94) B36(15.24,27.94) B38(17.78,27.94) B40(20.32,27.94) B42(22.86,27.94) B44(25.4,27.94) B46(27.94,27.94) BA1(-29.21,-21.59) BA3(-26.67,-21.59) BA5(-24.13,-21.59) BA7(-21.59,-21.59) BA9(-19.05,-21.59) BA11(-16.51,-21.59) BA13(-13.97,-21.59) BA15(-11.43,-21.59) BA17(-8.89,-21.59) BA19(-6.35,-21.59) BA21(-3.81,-21.59) BA23(-1.27,-21.59) BA25(1.27,-21.59) BA27(3.81,-21.59) BA29(6.35,-21.59) BA31(8.89,-21.59) BA33(11.43,-21.59) BA35(13.97,-21.59) BA37(16.51,-21.59) BA39(19.05,-21.59) BA41(21.59,-21.59) BA43(24.13,-21.59) BA45(26.67,-21.59) BA47(29.21,-21.59) BB2(-27.94,-22.86) BB4(-25.4,-22.86) BB6(-22.86,-22.86) BB8(-20.32,-22.86) BB10(-17.78,-22.86) BB12(-15.24,-22.86) BB14(-12.7,-22.86) BB16(-10.16,-22.86) BB18(-7.62,-22.86) BB20(-5.08,-22.86) BB22(-2.54,-22.86) BB24(0,-22.86) BB26(2.54,-22.86) BB28(5.08,-22.86) BB30(7.62,-22.86) BB32(10.16,-22.86) BB34(12.7,-22.86) BB36(15.24,-22.86) BB38(17.78,-22.86) BB40(20.32,-22.86) BB42(22.86,-22.86) BB44(25.4,-22.86) BB46(27.94,-22.86) BC1(-29.21,-24.13) BC3(-26.67,-24.13) BC5(-24.13,-24.13) BC7(-21.59,-24.13) BC9(-19.05,-24.13) BC11(-16.51,-24.13) BC13(-13.97,-24.13) BC15(-11.43,-24.13) BC17(-8.89,-24.13) BC19(-6.35,-24.13) BC21(-3.81,-24.13) BC23(-1.27,-24.13) BC25(1.27,-24.13) BC27(3.81,-24.13) BC29(6.35,-24.13) BC31(8.89,-24.13) BC33(11.43,-24.13) BC35(13.97,-24.13) BC37(16.51,-24.13) BC39(19.05,-24.13) BC41(21.59,-24.13) BC43(24.13,-24.13) BC45(26.67,-24.13) BC47(29.21,-24.13) BD2(-27.94,-25.4) BD4(-25.4,-25.4) BD6(-22.86,-25.4) BD8(-20.32,-25.4) BD10(-17.78,-25.4) BD12(-15.24,-25.4) BD14(-12.7,-25.4) BD16(-10.16,-25.4) BD18(-7.62,-25.4) BD20(-5.08,-25.4) BD22(-2.54,-25.4) BD24(0,-25.4) BD26(2.54,-25.4) BD28(5.08,-25.4) BD30(7.62,-25.4) BD32(10.16,-25.4) BD34(12.7,-25.4) BD36(15.24,-25.4) BD38(17.78,-25.4) BD40(20.32,-25.4) BD42(22.86,-25.4) BD44(25.4,-25.4) BD46(27.94,-25.4) BE1(-29.21,-26.67) BE3(-26.67,-26.67) BE5(-24.13,-26.67) BE7(-21.59,-26.67) BE9(-19.05,-26.67) BE11(-16.51,-26.67) BE13(-13.97,-26.67) BE15(-11.43,-26.67) BE17(-8.89,-26.67) BE19(-6.35,-26.67) BE21(-3.81,-26.67) BE23(-1.27,-26.67) BE25(1.27,-26.67) BE27(3.81,-26.67) BE29(6.35,-26.67) BE31(8.89,-26.67) BE33(11.43,-26.67) BE35(13.97,-26.67) BE37(16.51,-26.67) BE39(19.05,-26.67) BE41(21.59,-26.67) BE43(24.13,-26.67) BE45(26.67,-26.67) BE47(29.21,-26.67) BF2(-27.94,-27.94) BF4(-25.4,-27.94) BF6(-22.86,-27.94) BF8(-20.32,-27.94) BF10(-17.78,-27.94) BF12(-15.24,-27.94) BF14(-12.7,-27.94) BF16(-10.16,-27.94) BF18(-7.62,-27.94) BF20(-5.08,-27.94) BF22(-2.54,-27.94) BF24(0,-27.94) BF26(2.54,-27.94) BF28(5.08,-27.94) BF30(7.62,-27.94) BF32(10.16,-27.94) BF34(12.7,-27.94) BF36(15.24,-27.94) BF38(17.78,-27.94) BF40(20.32,-27.94) BF42(22.86,-27.94) BF44(25.4,-27.94) BF46(27.94,-27.94) BG1(-29.21,-29.21) BG3(-26.67,-29.21) BG5(-24.13,-29.21) BG7(-21.59,-29.21) BG9(-19.05,-29.21) BG11(-16.51,-29.21) BG13(-13.97,-29.21) BG15(-11.43,-29.21) BG17(-8.89,-29.21) BG19(-6.35,-29.21) BG21(-3.81,-29.21) BG23(-1.27,-29.21) BG25(1.27,-29.21) BG27(3.81,-29.21) BG29(6.35,-29.21) BG31(8.89,-29.21) BG33(11.43,-29.21) BG35(13.97,-29.21) BG37(16.51,-29.21) BG39(19.05,-29.21) BG41(21.59,-29.21) BG43(24.13,-29.21) BG45(26.67,-29.21) BG47(29.21,-29.21) C1(-29.21,26.67) C3(-26.67,26.67) C5(-24.13,26.67) C7(-21.59,26.67) C9(-19.05,26.67) C11(-16.51,26.67) C13(-13.97,26.67) C15(-11.43,26.67) C17(-8.89,26.67) C19(-6.35,26.67) C21(-3.81,26.67) C23(-1.27,26.67) C25(1.27,26.67) C27(3.81,26.67) C29(6.35,26.67) C31(8.89,26.67) C33(11.43,26.67) C35(13.97,26.67) C37(16.51,26.67) C39(19.05,26.67) C41(21.59,26.67) C43(24.13,26.67) C45(26.67,26.67) C47(29.21,26.67) D2(-27.94,25.4) D4(-25.4,25.4) D6(-22.86,25.4) D8(-20.32,25.4) D10(-17.78,25.4) D12(-15.24,25.4) D14(-12.7,25.4) D16(-10.16,25.4) D18(-7.62,25.4) D20(-5.08,25.4) D22(-2.54,25.4) D24(0,25.4) D26(2.54,25.4) D28(5.08,25.4) D30(7.62,25.4) D32(10.16,25.4) D34(12.7,25.4) D36(15.24,25.4) D38(17.78,25.4) D40(20.32,25.4) D42(22.86,25.4) D44(25.4,25.4) D46(27.94,25.4) E1(-29.21,24.13) E3(-26.67,24.13) E5(-24.13,24.13) E7(-21.59,24.13) E9(-19.05,24.13) E11(-16.51,24.13) E13(-13.97,24.13) E15(-11.43,24.13) E17(-8.89,24.13) E19(-6.35,24.13) E21(-3.81,24.13) E23(-1.27,24.13) E25(1.27,24.13) E27(3.81,24.13) E29(6.35,24.13) E31(8.89,24.13) E33(11.43,24.13) E35(13.97,24.13) E37(16.51,24.13) E39(19.05,24.13) E41(21.59,24.13) E43(24.13,24.13) E45(26.67,24.13) E47(29.21,24.13) F2(-27.94,22.86) F4(-25.4,22.86) F6(-22.86,22.86) F8(-20.32,22.86) F10(-17.78,22.86) F12(-15.24,22.86) F14(-12.7,22.86) F16(-10.16,22.86) F18(-7.62,22.86) F20(-5.08,22.86) F22(-2.54,22.86) F24(0,22.86) F26(2.54,22.86) F28(5.08,22.86) F30(7.62,22.86) F32(10.16,22.86) F34(12.7,22.86) F36(15.24,22.86) F38(17.78,22.86) F40(20.32,22.86) F42(22.86,22.86) F44(25.4,22.86) F46(27.94,22.86) G1(-29.21,21.59) G3(-26.67,21.59) G5(-24.13,21.59) G7(-21.59,21.59) G9(-19.05,21.59) G11(-16.51,21.59) G13(-13.97,21.59) G15(-11.43,21.59) G17(-8.89,21.59) G19(-6.35,21.59) G21(-3.81,21.59) G23(-1.27,21.59) G25(1.27,21.59) G27(3.81,21.59) G29(6.35,21.59) G31(8.89,21.59) G33(11.43,21.59) G35(13.97,21.59) G37(16.51,21.59) G39(19.05,21.59) G41(21.59,21.59) G43(24.13,21.59) G45(26.67,21.59) G47(29.21,21.59) H2(-27.94,20.32) H4(-25.4,20.32) H6(-22.86,20.32) H8(-20.32,20.32) H10(-17.78,20.32) H12(-15.24,20.32) H14(-12.7,20.32) H16(-10.16,20.32) H18(-7.62,20.32) H20(-5.08,20.32) H22(-2.54,20.32) H24(0,20.32) H26(2.54,20.32) H28(5.08,20.32) H30(7.62,20.32) H32(10.16,20.32) H34(12.7,20.32) H36(15.24,20.32) H38(17.78,20.32) H40(20.32,20.32) H42(22.86,20.32) H44(25.4,20.32) H46(27.94,20.32) J1(-29.21,19.05) J3(-26.67,19.05) J5(-24.13,19.05) J7(-21.59,19.05) J9(-19.05,19.05) J39(19.05,19.05) J41(21.59,19.05) J43(24.13,19.05) J45(26.67,19.05) J47(29.21,19.05) K2(-27.94,17.78) K4(-25.4,17.78) K6(-22.86,17.78) K8(-20.32,17.78) K40(20.32,17.78) K42(22.86,17.78) K44(25.4,17.78) K46(27.94,17.78) L1(-29.21,16.51) L3(-26.67,16.51) L5(-24.13,16.51) L7(-21.59,16.51) L9(-19.05,16.51) L39(19.05,16.51) L41(21.59,16.51) L43(24.13,16.51) L45(26.67,16.51) L47(29.21,16.51) M2(-27.94,15.24) M4(-25.4,15.24) M6(-22.86,15.24) M8(-20.32,15.24) M40(20.32,15.24) M42(22.86,15.24) M44(25.4,15.24) M46(27.94,15.24) N1(-29.21,13.97) N3(-26.67,13.97) N5(-24.13,13.97) N7(-21.59,13.97) N9(-19.05,13.97) N39(19.05,13.97) N41(21.59,13.97) N43(24.13,13.97) N45(26.67,13.97) N47(29.21,13.97) P2(-27.94,12.7) P4(-25.4,12.7) P6(-22.86,12.7) P8(-20.32,12.7) P40(20.32,12.7) P42(22.86,12.7) P44(25.4,12.7) P46(27.94,12.7) R1(-29.21,11.43) R3(-26.67,11.43) R5(-24.13,11.43) R7(-21.59,11.43) R9(-19.05,11.43) R39(19.05,11.43) R41(21.59,11.43) R43(24.13,11.43) R45(26.67,11.43) R47(29.21,11.43) T2(-27.94,10.16) T4(-25.4,10.16) T6(-22.86,10.16) T8(-20.32,10.16) T40(20.32,10.16) T42(22.86,10.16) T44(25.4,10.16) T46(27.94,10.16) U1(-29.21,8.89) U3(-26.67,8.89) U5(-24.13,8.89) U7(-21.59,8.89) U9(-19.05,8.89) U39(19.05,8.89) U41(21.59,8.89) U43(24.13,8.89) U45(26.67,8.89) U47(29.21,8.89) V2(-27.94,7.62) V4(-25.4,7.62) V6(-22.86,7.62) V8(-20.32,7.62) V40(20.32,7.62) V42(22.86,7.62) V44(25.4,7.62) V46(27.94,7.62) W1(-29.21,6.35) W3(-26.67,6.35) W5(-24.13,6.35) W7(-21.59,6.35) W9(-19.05,6.35) W39(19.05,6.35) W41(21.59,6.35) W43(24.13,6.35) W45(26.67,6.35) W47(29.21,6.35) Y2(-27.94,5.08) Y4(-25.4,5.08) Y6(-22.86,5.08) Y8(-20.32,5.08) Y40(20.32,5.08) Y42(22.86,5.08) Y44(25.4,5.08) Y46(27.94,5.08)
Top Overlay:
  circle w0.25: c-31.13,29.21 r0.125
  lines w0.2: -30.48,-30.48 -30.48,29.48 -29.48,30.48 30.48,30.48 30.48,-30.48 -30.48,-30.48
